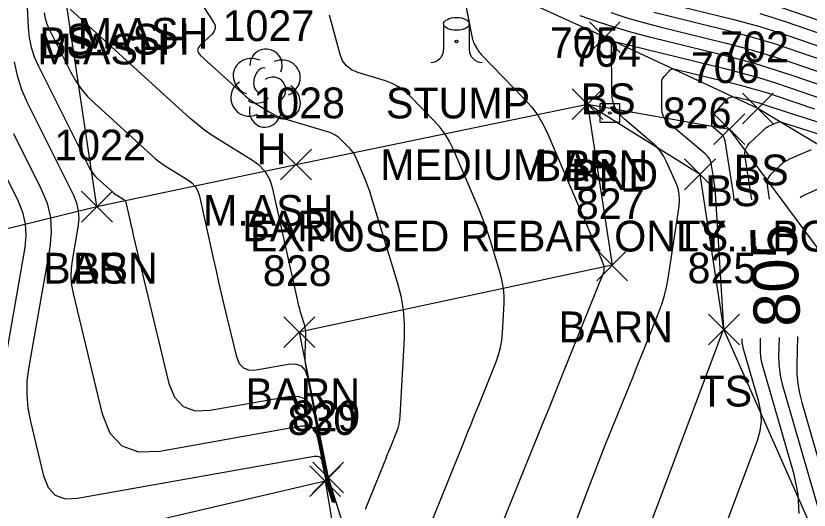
# Model space of a CAD drawing. Extents: x 1650836 to 1652450, y 332578 to 333908.
# Drawn here: x 1651986.8 to 1652038.3, y 332770.4 to 332802.5 of the extents above; entities that cross this region are included whole.
import ezdxf

# ---------------------------------------------------------------- set-up
doc = ezdxf.new("R2010")
doc.units = 0
for name, color, linetype in [('L_A', 7, 'Continuous'), ('L_C', 7, 'Continuous'), ('L_I', 7, 'Continuous'), ('L_TIC', 7, 'Continuous'), ('LBC', 7, 'Continuous'), ('LELB', 7, 'Continuous'), ('LSOGCMA', 7, 'Continuous'), ('LSOGCMA_T', 7, 'Continuous'), ('LSOGCMI', 7, 'Continuous'), ('LTD', 7, 'Continuous'), ('LTS', 7, 'Continuous'), ('LW', 7, 'Continuous'), ('M_A', 7, 'Continuous'), ('M_C', 7, 'Continuous'), ('M_I', 7, 'Continuous'), ('MHBP', 7, 'Continuous')]:
    doc.layers.add(name, color=color, linetype=linetype)

msp = doc.modelspace()

# ---------------------------------------------------------------- linework, layer by layer
at = {"layer": 'L_TIC'}
for points in [[(1652024.062, 332800.1), (1652026.062, 332802.1)], [(1652026.062, 332800.1), (1652024.062, 332802.1)], [(1652022.947, 332795.746), (1652024.947, 332797.746)], [(1652024.947, 332795.746), (1652022.947, 332797.746)], [(1652022.947, 332795.746), (1652024.947, 332797.746)], [(1652024.947, 332795.746), (1652022.947, 332797.746)], [(1652033.993, 332795.475), (1652035.993, 332797.475)], [(1652035.993, 332795.475), (1652033.993, 332797.475)], [(1652032.145, 332794.123), (1652034.145, 332796.123)], [(1652034.145, 332794.123), (1652032.145, 332796.123)], [(1652004.024, 332791.832), (1652006.024, 332793.832)], [(1652006.024, 332791.832), (1652004.024, 332793.832)], [(1652030.244, 332791.189), (1652032.244, 332793.189)], [(1652032.244, 332791.189), (1652030.244, 332793.189)], [(1651991.104, 332789.093), (1651993.104, 332791.093)], [(1651993.104, 332789.093), (1651991.104, 332791.093)], [(1651991.104, 332789.093), (1651993.104, 332791.093)], [(1651993.104, 332789.093), (1651991.104, 332791.093)], [(1652024.548, 332785.282), (1652026.548, 332787.282)], [(1652026.548, 332785.282), (1652024.548, 332787.282)], [(1652004.235, 332780.934), (1652006.235, 332782.934)], [(1652006.235, 332780.934), (1652004.235, 332782.934)], [(1652031.797, 332781.109), (1652033.797, 332783.109)], [(1652033.797, 332781.109), (1652031.797, 332783.109)], [(1652006.106, 332771.495), (1652008.106, 332773.495)], [(1652008.106, 332771.495), (1652006.106, 332773.495)], [(1652006.106, 332771.495), (1652008.106, 332773.495)], [(1652008.106, 332771.495), (1652006.106, 332773.495)], [(1652005.921, 332771.261), (1652007.921, 332773.261)], [(1652007.921, 332771.261), (1652005.921, 332773.261)], [(1652005.921, 332771.261), (1652007.921, 332773.261)], [(1652007.921, 332771.261), (1652005.921, 332773.261)]]:
    msp.add_lwpolyline(points, dxfattribs=at)
at = {"layer": 'LBC'}
for points in [[(1652023.947, 332796.746), (1652025.548, 332786.282), (1652005.235, 332781.934), (1652007.106, 332772.495), (1652006.921, 332772.261), (1651982.996, 332766.671), (1651977.172, 332765.646), (1651973.519, 332785.08), (1651981.067, 332787.388), (1651992.104, 332790.093), (1652005.024, 332792.832)], [(1652005.024, 332792.832), (1652023.947, 332796.746)]]:
    msp.add_lwpolyline(points, dxfattribs=at)
at = {"layer": 'LELB'}
for points in [[(1652048.756, 332662.461), (1652082.555, 332678.298), (1652130.366, 332703.201), (1652148.083, 332715.406), (1652159.47, 332726.367), (1652148.02, 332734.227), (1652128.413, 332739.339), (1652116.951, 332747.33), (1652106.793, 332756.875), (1652094.604, 332761.138), (1652083.802, 332764.466), (1652074.482, 332770.284), (1652065.17, 332770.428), (1652062.989, 332774.387), (1652054.537, 332784.724), (1652034.993, 332796.475), (1652025.062, 332801.1), (1652009.772, 332808.074), (1651988.967, 332816.401), (1651980.006, 332832.954), (1651960.575, 332843.477), (1651932.852, 332862.75), (1651890.753, 332886.019), (1651847.527, 332911.35)], [(1651992.104, 332790.093), (1651989.915, 332804.738), (1651988.967, 332816.401), (1651977.078, 332830.976), (1651959.162, 332840.786), (1651931.328, 332859.703), (1651889.406, 332883.733), (1651845.231, 332908.813)], [(1652023.947, 332796.746), (1652033.145, 332795.123), (1652040.892, 332784.647), (1652044.285, 332773.47), (1652048.825, 332762.633), (1652060.903, 332762.254), (1652066.549, 332756.035)], [(1652031.244, 332792.189), (1652023.947, 332796.746)], [(1652046.201, 332751.794), (1652032.797, 332782.109), (1652031.244, 332792.189)], [(1652007.106, 332772.495), (1652011.431, 332758.675), (1652018.837, 332745.557)]]:
    msp.add_lwpolyline(points, dxfattribs=at)
at = {"layer": 'LSOGCMA'}
for points in [[(1651987.515, 332804.387), (1651987.645, 332801.738), (1651987.711, 332801.085), (1651987.842, 332800.448), (1651988.039, 332799.829), (1651988.303, 332799.228), (1651991.556, 332792.712), (1651991.677, 332792.494), (1651991.816, 332792.291), (1651991.974, 332792.102), (1651992.15, 332791.926), (1651993.109, 332791.052), (1651993.186, 332790.985), (1651993.266, 332790.921), (1651993.349, 332790.862), (1651993.436, 332790.807), (1651993.786, 332790.593), (1651993.865, 332790.534), (1651993.928, 332790.463), (1651993.975, 332790.38), (1651994.005, 332790.286), (1651994.259, 332789.141), (1651994.309, 332788.917), (1651994.36, 332788.693), (1651994.412, 332788.469), (1651994.465, 332788.246), (1651996.78, 332778.613), (1651997.138, 332777.705), (1651997.703, 332777.111), (1651998.473, 332776.832), (1651999.448, 332776.866), (1652004.506, 332777.766), (1652005.141, 332777.788), (1652005.634, 332777.603), (1652005.985, 332777.21), (1652006.194, 332776.611), (1652006.75, 332773.782), (1652006.895, 332773.088), (1652007.058, 332772.399), (1652007.239, 332771.714), (1652007.437, 332771.034), (1652007.484, 332770.88)], [(1652062.441, 332794.127), (1652036.56, 332803.009)], [(1652038.451, 332793.792), (1652037.088, 332793.19), (1652036.906, 332793.1), (1652036.734, 332792.995), (1652036.571, 332792.876), (1652036.418, 332792.743), (1652035.826, 332792.179), (1652035.701, 332792.03), (1652035.621, 332791.867), (1652035.585, 332791.688), (1652035.595, 332791.494), (1652035.741, 332790.583)], [(1652036.372, 332781.601), (1652036.344, 332780.405), (1652036.35, 332779.935), (1652036.393, 332779.469), (1652036.47, 332779.007), (1652036.584, 332778.551), (1652039.972, 332766.816)]]:
    msp.add_lwpolyline(points, dxfattribs=at)
at = {"layer": 'LSOGCMI'}
for points in [[(1651995.893, 332807.934), (1651999.669, 332802.087), (1651999.767, 332801.876), (1651999.784, 332801.676), (1651999.719, 332801.486), (1651999.573, 332801.306), (1651998.826, 332800.605), (1651998.686, 332800.43), (1651998.64, 332800.256), (1651998.689, 332800.082), (1651998.831, 332799.91), (1652001.541, 332797.439), (1652001.745, 332797.262), (1652001.956, 332797.096), (1652002.175, 332796.939), (1652002.402, 332796.793), (1652003.325, 332796.231), (1652003.559, 332796.098), (1652003.8, 332795.981), (1652004.048, 332795.879), (1652004.304, 332795.793), (1652007.188, 332794.922), (1652007.382, 332794.851), (1652007.562, 332794.757), (1652007.728, 332794.641), (1652007.881, 332794.502), (1652008.465, 332793.903), (1652008.603, 332793.749), (1652008.725, 332793.583), (1652008.831, 332793.406), (1652008.921, 332793.219), (1652009.483, 332791.9), (1652009.6, 332791.614), (1652009.71, 332791.326), (1652009.811, 332791.035), (1652009.905, 332790.741), (1652011.591, 332785.195), (1652011.822, 332784.298), (1652011.973, 332783.391), (1652012.045, 332782.475), (1652012.036, 332781.549), (1652011.772, 332776.51), (1652011.746, 332776.238), (1652011.699, 332775.972), (1652011.63, 332775.71), (1652011.538, 332775.453), (1652011.129, 332774.434), (1652011.027, 332774.179), (1652010.924, 332773.925), (1652010.822, 332773.67), (1652010.719, 332773.416), (1652009.51, 332770.422)], [(1652015.824, 332804.275), (1652016.457, 332801.059), (1652016.481, 332800.959), (1652016.512, 332800.861), (1652016.55, 332800.766), (1652016.596, 332800.673), (1652016.794, 332800.308), (1652016.847, 332800.219), (1652016.905, 332800.134), (1652016.969, 332800.053), (1652017.038, 332799.977), (1652019.841, 332797.106), (1652020.305, 332796.585), (1652020.715, 332796.028), (1652021.072, 332795.435), (1652021.374, 332794.806), (1652024.888, 332786.558), (1652024.903, 332786.52), (1652024.918, 332786.481), (1652024.932, 332786.443), (1652024.944, 332786.403), (1652024.994, 332786.239), (1652025.003, 332786.203), (1652025.009, 332786.167), (1652025.012, 332786.131), (1652025.012, 332786.094), (1652025.004, 332785.946), (1652025.001, 332785.91), (1652024.994, 332785.874), (1652024.985, 332785.838), (1652024.973, 332785.804), (1652022.632, 332779.976), (1652022.237, 332778.993), (1652021.842, 332778.01), (1652021.446, 332777.028), (1652021.049, 332776.046), (1652016.662, 332765.188)], [(1652007.595, 332770.855), (1652007.392, 332771.553), (1652007.143, 332772.494), (1652006.919, 332773.441), (1652006.719, 332774.394), (1652005.684, 332779.664), (1652005.646, 332779.898), (1652005.622, 332780.133), (1652005.612, 332780.369), (1652005.617, 332780.606), (1652005.67, 332781.611), (1652005.672, 332781.821), (1652005.656, 332782.028), (1652005.622, 332782.233), (1652005.57, 332782.435), (1652005.325, 332783.242), (1652005.265, 332783.444), (1652005.21, 332783.647), (1652005.158, 332783.851), (1652005.111, 332784.056), (1652003.519, 332791.254), (1652003.337, 332791.82), (1652003.057, 332792.316), (1652002.678, 332792.742), (1652002.202, 332793.098), (1652000.099, 332794.38), (1651999.582, 332794.712), (1651999.082, 332795.068), (1651998.601, 332795.448), (1651998.137, 332795.851), (1651990.374, 332802.927)], [(1652029.795, 332803.147), (1652033.358, 332802.267), (1652034.246, 332802.037), (1652035.128, 332801.788), (1652036.005, 332801.52), (1652036.876, 332801.231), (1652054.495, 332795.185)], [(1651988.671, 332802.675), (1651988.745, 332802.316), (1651988.856, 332801.966), (1651989.005, 332801.627), (1651990.394, 332798.845), (1651990.704, 332798.288), (1651991.062, 332797.766), (1651991.467, 332797.279), (1651991.918, 332796.828), (1651995.623, 332793.451), (1651995.893, 332793.216), (1651996.174, 332792.995), (1651996.466, 332792.787), (1651996.767, 332792.593), (1651997.994, 332791.845), (1651998.272, 332791.638), (1651998.492, 332791.39), (1651998.656, 332791.1), (1651998.762, 332790.77), (1651999.67, 332786.665), (1651999.835, 332785.928), (1652000.003, 332785.191), (1652000.175, 332784.454), (1652000.35, 332783.719), (1652001.163, 332780.335), (1652001.336, 332779.897), (1652001.607, 332779.611), (1652001.978, 332779.477), (1652002.448, 332779.494), (1652004.525, 332779.863), (1652004.992, 332779.879), (1652005.355, 332779.743), (1652005.613, 332779.454), (1652005.767, 332779.013), (1652006.689, 332774.318), (1652006.886, 332773.38), (1652007.107, 332772.448), (1652007.351, 332771.522), (1652007.542, 332770.867)], [(1652010.741, 332762.001), (1652015.884, 332774.731), (1652016.134, 332775.349), (1652016.383, 332775.968), (1652016.632, 332776.586), (1652016.881, 332777.205), (1652018.01, 332780.018), (1652018.171, 332780.472), (1652018.294, 332780.934), (1652018.377, 332781.405), (1652018.422, 332781.885), (1652018.524, 332783.821), (1652018.528, 332784.303), (1652018.491, 332784.779), (1652018.413, 332785.251), (1652018.293, 332785.717), (1652017.636, 332787.877), (1652017.472, 332788.39), (1652017.296, 332788.897), (1652017.105, 332789.399), (1652016.901, 332789.897), (1652015.219, 332793.845), (1652014.984, 332794.335), (1652014.706, 332794.796), (1652014.387, 332795.229), (1652014.026, 332795.635), (1652012.391, 332797.31), (1652012.047, 332797.622), (1652011.672, 332797.883), (1652011.267, 332798.095), (1652010.832, 332798.256), (1652009.029, 332798.8), (1652008.619, 332798.976), (1652008.292, 332799.231), (1652008.046, 332799.566), (1652007.882, 332799.981), (1652007.191, 332802.531)], [(1652043.687, 332796.389), (1652037.35, 332798.564), (1652036.207, 332798.943), (1652035.057, 332799.295), (1652033.899, 332799.622), (1652032.734, 332799.923), (1652028.059, 332801.078), (1652026.895, 332801.383), (1652025.741, 332801.721), (1652024.597, 332802.091), (1652023.464, 332802.494)], [(1652025.45, 332802.7), (1652026.503, 332802.36), (1652027.566, 332802.049), (1652028.637, 332801.768), (1652032.942, 332800.705), (1652034.015, 332800.427), (1652035.081, 332800.126), (1652036.14, 332799.802), (1652037.192, 332799.453), (1652046.548, 332796.242)], [(1652050.521, 332795.714), (1652037.034, 332800.342), (1652036.072, 332800.661), (1652035.104, 332800.957), (1652034.13, 332801.232), (1652033.15, 332801.486), (1652029.216, 332802.458), (1652028.237, 332802.714)], [(1652058.468, 332794.656), (1652036.718, 332802.12), (1652035.937, 332802.379), (1652035.152, 332802.619)], [(1652019.572, 332759.969), (1652023.746, 332771.121), (1652024.086, 332772.02), (1652024.432, 332772.917), (1652024.784, 332773.812), (1652025.141, 332774.705), (1652026.874, 332778.994), (1652027.088, 332779.523), (1652027.301, 332780.053), (1652027.514, 332780.583), (1652027.727, 332781.113), (1652028.579, 332783.233), (1652028.775, 332783.767), (1652028.941, 332784.31), (1652029.074, 332784.861), (1652029.176, 332785.422), (1652029.891, 332790.134), (1652029.922, 332790.517), (1652029.899, 332790.893), (1652029.821, 332791.261), (1652029.688, 332791.621), (1652029.046, 332793.048), (1652028.869, 332793.392), (1652028.656, 332793.71), (1652028.409, 332794.001), (1652028.127, 332794.266), (1652026.316, 332795.793), (1652025.965, 332796.154), (1652025.714, 332796.563), (1652025.563, 332797.018), (1652025.512, 332797.52), (1652025.508, 332800.741), (1652025.509, 332800.755), (1652025.512, 332800.768), (1652025.518, 332800.78), (1652025.527, 332800.792), (1652025.565, 332800.835), (1652025.575, 332800.844), (1652025.586, 332800.85), (1652025.599, 332800.851), (1652025.612, 332800.85), (1652032.951, 332799.037), (1652033.997, 332798.767), (1652035.036, 332798.473), (1652036.068, 332798.157), (1652037.094, 332797.817), (1652041.183, 332796.414)], [(1652007.431, 332770.892), (1652007.255, 332771.467), (1652007.127, 332771.907), (1652007.01, 332772.35), (1652006.904, 332772.796), (1652006.81, 332773.245), (1652006.451, 332775.076), (1652006.315, 332775.465), (1652006.088, 332775.719), (1652005.769, 332775.839), (1652005.358, 332775.824), (1651996.176, 332774.191), (1651994.818, 332774.142), (1651993.746, 332774.531), (1651992.961, 332775.358), (1651992.461, 332776.621), (1651990.581, 332784.447), (1651990.48, 332784.982), (1651990.436, 332785.519), (1651990.447, 332786.057), (1651990.515, 332786.598), (1651990.897, 332788.762), (1651990.95, 332789.296), (1651990.917, 332789.819), (1651990.8, 332790.329), (1651990.597, 332790.826), (1651987.6, 332796.828), (1651987.223, 332797.692), (1651986.939, 332798.581), (1651986.751, 332799.494)], [(1652023.971, 332758.619), (1652032.737, 332782.036), (1652032.744, 332782.054), (1652032.763, 332782.103), (1652032.769, 332782.117), (1652032.772, 332782.124), (1652032.773, 332782.132), (1652032.781, 332782.181), (1652032.782, 332782.19), (1652032.782, 332782.2), (1652032.783, 332782.209), (1652032.782, 332782.219), (1652032.238, 332790.98), (1652032.221, 332791.207), (1652032.198, 332791.434), (1652032.171, 332791.66), (1652032.137, 332791.885), (1652031.993, 332792.784), (1652031.94, 332792.999), (1652031.852, 332793.195), (1652031.73, 332793.371), (1652031.573, 332793.527), (1652029.234, 332795.498), (1652029.028, 332795.711), (1652028.88, 332795.951), (1652028.791, 332796.219), (1652028.761, 332796.514), (1652028.759, 332798.127), (1652028.769, 332798.243), (1652028.798, 332798.351), (1652028.848, 332798.452), (1652028.917, 332798.546), (1652029.233, 332798.905), (1652029.316, 332798.979), (1652029.409, 332799.025), (1652029.511, 332799.041), (1652029.623, 332799.027), (1652033.777, 332798.001), (1652034.4, 332797.84), (1652035.019, 332797.665), (1652035.633, 332797.476), (1652036.244, 332797.274), (1652038.679, 332796.439)], [(1652033.469, 332790.489), (1652033.413, 332790.949), (1652033.335, 332791.476), (1652032.871, 332794.37), (1652032.839, 332794.496), (1652032.788, 332794.611), (1652032.716, 332794.714), (1652032.624, 332794.806), (1652032.133, 332795.22), (1652032.08, 332795.275), (1652032.041, 332795.337), (1652032.018, 332795.407), (1652032.011, 332795.483), (1652032.01, 332795.802), (1652032.017, 332795.88), (1652032.036, 332795.952), (1652032.069, 332796.02), (1652032.116, 332796.082), (1652032.901, 332796.974), (1652033.058, 332797.115), (1652033.232, 332797.2), (1652033.424, 332797.23), (1652033.634, 332797.204), (1652034.604, 332796.964), (1652034.803, 332796.912), (1652035.002, 332796.856), (1652035.199, 332796.796), (1652035.394, 332796.731), (1652036.175, 332796.463), (1652036.37, 332796.397), (1652036.566, 332796.332), (1652036.762, 332796.268), (1652036.958, 332796.205), (1652059.028, 332789.196)], [(1652034.617, 332790.536), (1652034.168, 332793.339), (1652034.155, 332793.585), (1652034.2, 332793.813), (1652034.302, 332794.02), (1652034.461, 332794.209), (1652035.43, 332795.131), (1652035.512, 332795.203), (1652035.599, 332795.267), (1652035.691, 332795.323), (1652035.788, 332795.371), (1652036.189, 332795.548), (1652036.289, 332795.582), (1652036.391, 332795.597), (1652036.493, 332795.593), (1652036.597, 332795.57), (1652058.137, 332788.73)], [(1651986.691, 332794.844), (1651988.494, 332791.234), (1651988.866, 332790.32), (1651989.082, 332789.383), (1651989.141, 332788.424), (1651989.044, 332787.442), (1651987.675, 332779.679), (1651987.563, 332778.787), (1651987.544, 332777.897), (1651987.617, 332777.01), (1651987.783, 332776.126), (1651988.632, 332772.596), (1651988.929, 332771.843), (1651989.397, 332771.351), (1651990.035, 332771.12), (1651990.843, 332771.148), (1652006.21, 332773.882), (1652006.397, 332773.889), (1652006.542, 332773.834), (1652006.646, 332773.719), (1652006.707, 332773.542), (1652006.871, 332772.709), (1652006.914, 332772.504), (1652006.962, 332772.301), (1652007.015, 332772.1), (1652007.073, 332771.899), (1652007.372, 332770.919), (1652007.376, 332770.905)], [(1651985.548, 332793.328), (1651986.984, 332790.452), (1651987.281, 332789.724), (1651987.453, 332788.978), (1651987.5, 332788.213), (1651987.423, 332787.431), (1651984.495, 332770.84)], [(1652040.713, 332792.037), (1652038.113, 332790.887), (1652037.98, 332790.822), (1652037.854, 332790.745), (1652037.745, 332790.665)], [(1652031.809, 332743.206), (1652030.742, 332746.623), (1652030.499, 332747.391), (1652030.248, 332748.157), (1652029.991, 332748.92), (1652029.727, 332749.682), (1652028.335, 332753.633), (1652028.096, 332754.544), (1652028.022, 332755.454), (1652028.114, 332756.362), (1652028.37, 332757.268), (1652034.971, 332774.903), (1652035.152, 332775.525), (1652035.228, 332776.151), (1652035.2, 332776.781), (1652035.068, 332777.415), (1652034.054, 332780.929), (1652034.016, 332781.08), (1652033.99, 332781.233), (1652033.976, 332781.388), (1652033.975, 332781.502)], [(1652037.675, 332770.152), (1652037.619, 332771.416), (1652037.355, 332772.688), (1652035.319, 332779.74), (1652035.243, 332780.044), (1652035.191, 332780.351), (1652035.163, 332780.661), (1652035.159, 332780.975), (1652035.173, 332781.552)], [(1652037.572, 332781.65), (1652037.529, 332779.836), (1652037.537, 332779.208), (1652037.594, 332778.586), (1652037.697, 332777.971), (1652037.849, 332777.362), (1652043.006, 332759.5)]]:
    msp.add_lwpolyline(points, dxfattribs=at)
at = {"layer": 'LTD'}
msp.add_line((1652003.032, 332797.849), (1652003.032, 332797.849), dxfattribs=at)
msp.add_line((1652003.032, 332797.849), (1652003.032, 332797.849), dxfattribs=at)
msp.add_arc((1652003.078, 332799.283), 1.047, 335.5272, 180.9563, dxfattribs=at)
for centre, major_axis, ratio, start_param, end_param in [((1652002.24, 332798.516), (1.21, -0.512), 0.895232, 1.570796, 4.712389), ((1652004.073, 332798.433), (-1.141, -0.483), 0.949671, 1.570796, 4.712389), ((1652002.823, 332798.308), (-0.208, -0.792), 0.645439, 3.141593, 6.283185), ((1652001.948, 332797.141), (0.584, -1.042), 0.959034, 3.141593, 6.283185), ((1652003.532, 332797.683), (-0.5, 0.667), 0.989748, 3.141593, 6.283185), ((1652004.032, 332797.016), (-1.09, 0.792), 0.841452, 1.570796, 4.712389), ((1652002.573, 332797.099), (-0.625, -0.083), 0.423636, 0, 3.141593), ((1652003.032, 332796.349), (0.265, 1.061), 0.942809, 1.570796, 4.712389)]:
    msp.add_ellipse(centre, major_axis=major_axis, ratio=ratio, start_param=start_param, end_param=end_param, dxfattribs=at)
at = {"layer": 'LTS'}
for p, q in [((1652014.605, 332801.965), (1652014.605, 332800.298)), ((1652016.271, 332801.798), (1652016.271, 332801.965)), ((1652016.271, 332801.965), (1652016.271, 332800.298)), ((1652015.438, 332800.823), (1652015.438, 332800.823)), ((1652015.438, 332800.823), (1652015.438, 332800.823)), ((1652015.438, 332800.798), (1652015.438, 332800.798))]:
    msp.add_line(p, q, dxfattribs=at)
msp.add_circle((1652015.438, 332800.823), 0.0833, dxfattribs=at)
for centre, start, end in [((1652013.771, 332800.298), 270, 360), ((1652017.105, 332800.298), 180, 270)]:
    msp.add_arc(centre, 0.833, start, end, dxfattribs=at)
msp.add_ellipse((1652015.438, 332801.965), major_axis=(-0.833, 0), ratio=0.5, dxfattribs=at)
at = {"layer": 'LW'}
msp.add_lwpolyline([(1652006.921, 332772.261), (1652009.261, 332758.462)], dxfattribs=at)
at = {"layer": 'MHBP'}
msp.add_lwpolyline([(1652024.763, 332796.804), (1652026.013, 332796.804), (1652026.013, 332795.554), (1652024.763, 332795.554)], close=True, dxfattribs=at)
msp.add_circle((1652025.388, 332796.179), 0.0833, dxfattribs=at)

# ---------------------------------------------------------------- texts
at = {"layer": 'L_A'}
for s, p in [('BS', (1651988.356, 332799.738)), ('STUMP', (1652010.859, 332795.825)), ('BS', (1652023.503, 332796.1)), ('H', (1652002.465, 332792.849)), ('BARN', (1652020.458, 332791.746)), ('BS', (1652022.388, 332791.746)), ('BS', (1652033.434, 332791.475)), ('BS', (1652031.586, 332790.123)), ('BARN', (1652001.536, 332787.832)), ('TS', (1652029.654, 332787.189)), ('BARN', (1651988.616, 332785.093)), ('BS', (1651990.545, 332785.093)), ('BARN', (1652022.059, 332781.282)), ('TS', (1652031.207, 332777.109)), ('BARN', (1652001.747, 332776.934))]:
    msp.add_text(s, height=2, dxfattribs=at).set_placement(p)
at = {"layer": 'L_C'}
for s, p in [('M.ASH', (1651990.858, 332800.354)), ('S.ASH', (1651990.096, 332799.972)), ('M.ASH', (1651988.232, 332799.333)), ('MEDIUM', (1652010.489, 332791.825)), ('M.ASH', (1651998.984, 332788.849))]:
    msp.add_text(s, height=2, dxfattribs=at).set_placement(p)
at = {"layer": 'L_I'}
for s, p in [('1027', (1652000.26, 332800.849)), ('705', (1652021.506, 332799.746)), ('705', (1652021.506, 332799.746)), ('702', (1652032.553, 332799.475)), ('706', (1652030.649, 332798.123)), ('1028', (1652002.253, 332795.832)), ('826', (1652028.827, 332795.189)), ('1022', (1651989.333, 332793.093)), ('1022', (1651989.333, 332793.093)), ('827', (1652023.185, 332789.282)), ('828', (1652002.873, 332784.934)), ('825', (1652030.435, 332785.109)), ('830', (1652004.473, 332775.261)), ('830', (1652004.473, 332775.261)), ('829', (1652004.736, 332775.495)), ('829', (1652004.736, 332775.495))]:
    msp.add_text(s, height=2, dxfattribs=at).set_placement(p)
at = {"layer": 'LSOGCMA_T'}
msp.add_text('805', height=3, rotation=92.355, dxfattribs=at).set_placement((1652037.758, 332782.332))
at = {"layer": 'M_A'}
msp.add_text('BND', height=2, dxfattribs=at).set_placement((1652022.876, 332791.179))
at = {"layer": 'M_C'}
msp.add_text('EXPOSED REBAR ONLY... BOUND', height=2, dxfattribs=at).set_placement((1652002.042, 332787.179))
at = {"layer": 'M_I'}
msp.add_text('704', height=2, dxfattribs=at).set_placement((1652022.947, 332799.179))

doc.saveas('drawing.dxf')
